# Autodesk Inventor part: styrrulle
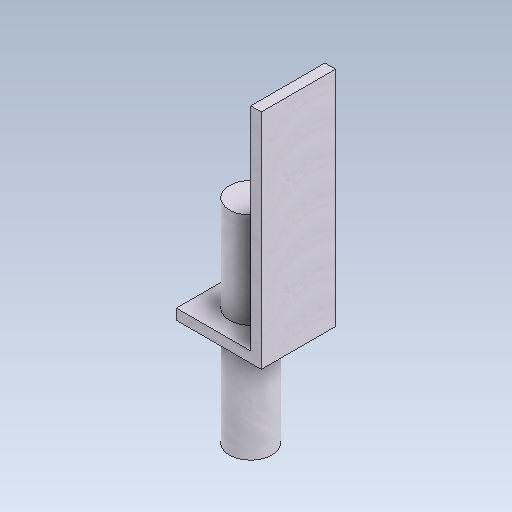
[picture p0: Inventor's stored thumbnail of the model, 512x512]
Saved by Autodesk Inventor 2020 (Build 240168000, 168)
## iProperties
Created: 2019-06
Part Number: styrrulle
Material: Aluminum 6061, Welded
Document SubType Name: Modeling
Designer: cl
Density: 2.7 g/cm^3
Appearance: Weld - Aluminum
Author: cl
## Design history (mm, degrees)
sketch "Sketch1"
  geometry: L1 (0, 0)-(40, 0); L2 (40, 0)-(40, -35); L3 (40, -35)-(0, -35); L4 (0, -35)-(0, 0)
  constraints: 8 end point, 2 parallel, 1 horizontal, 1 perpendicular
  dimensions: "d0" = 40 distance of L2.end L3.end; "d1" = 35 distance of L1.end L2.end
extrude "Extrusion1" new body sketch "Sketch1" distance "d2" = 5; taper "d3" = 0 deg
sketch "Sketch2"
  geometry: L1 (0, 0)-(0, 35) reference; L2 (0, 35)-(-40, 35) reference; L3 (0, 0)-(-5, 0); L4 (-5, 0)-(-5, 35); L5 (-5, 35)-(0, 35); L6 (0, 35)-(0, 0); 1 further point
  constraints: 8 end point, 2 parallel, 1 horizontal, 1 perpendicular, 1 point on line
  dimensions: "d4" = 5 distance of L4.end L5.end
extrude "Extrusion2" join sketch "Sketch2" distance "d5" = 100; taper "d6" = 0 deg
sketch "Sketch3"
  geometry: L1 (-40, -35)-(-40, 0) reference; L2 (-40, 0)-(0, 0) reference; C1 r 10 at (-22.5, -17.5)
  constraints: 1 centre point
  dimensions: "d7" = 17.5 distance from line of L1 C1.centre; "d8" = 17.5 distance from line of L2 C1.centre; "d9" = 20 diameter of C1
extrude "Extrusion3" join sketch "Sketch3" distance "d10" = 50; taper "d12" = 0 deg; dims "d11" = 50, "d13" = 0
body "Solid1"
